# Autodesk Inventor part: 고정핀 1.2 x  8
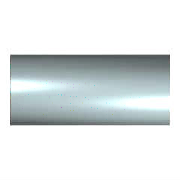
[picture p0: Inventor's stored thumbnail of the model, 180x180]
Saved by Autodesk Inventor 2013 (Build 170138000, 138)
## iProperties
IsCustomPart: 1
Created: 2012-02
Part Number: 고정핀 1.2 x  8
Material: 강철, 연강
Description: 평행 핀
Document SubType Name: Modeling
Standard: KS B 1320
Designer: P15F
Standards Organization: KS
Language: ko-KR
Size Designation: C 1.2 x  8
Categories: <MemberInstance><Categories><Category DisplayName="조임쇠" InternalName="e4da775c-781d-43d5-af7c-5136215cf5a6" Mnemonic="FSTN"><Category DisplayName="핀" InternalNa
Density: 1 g/cm^3
Author: P15F
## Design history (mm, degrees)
sketch "스케치1"
  geometry: C1 r 0.6 at (0, 0); 1 further point
  constraints: 1 centre point, 1 coincident
  dimensions: "d1" = 1.2 diameter of C1 (= NND)
extrude "본체" new body sketch "스케치1" distance "d2" = 8 (= NLG); taper "d3" = 0 deg
node "작업 평면1"
body "Solid1"
other parameters: "NND" = 1.2 [user parameter; used in 1 equation term], "NLG" = 8 [user parameter; used in 1 equation term], "d8" = 0, "d9" = 0, "d10" = 0
